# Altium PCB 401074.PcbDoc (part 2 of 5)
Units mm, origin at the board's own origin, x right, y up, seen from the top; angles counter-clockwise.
Board outline 70.15 x 35.15 mm, 6 copper layers (Top Layer, Mid-Layer1, Mid-Layer2, Mid-Layer3, Mid-Layer4, Bottom Layer), stack 1.549 mm thick; 239 components, 182 nets, 1034 pads, 1263 vias.
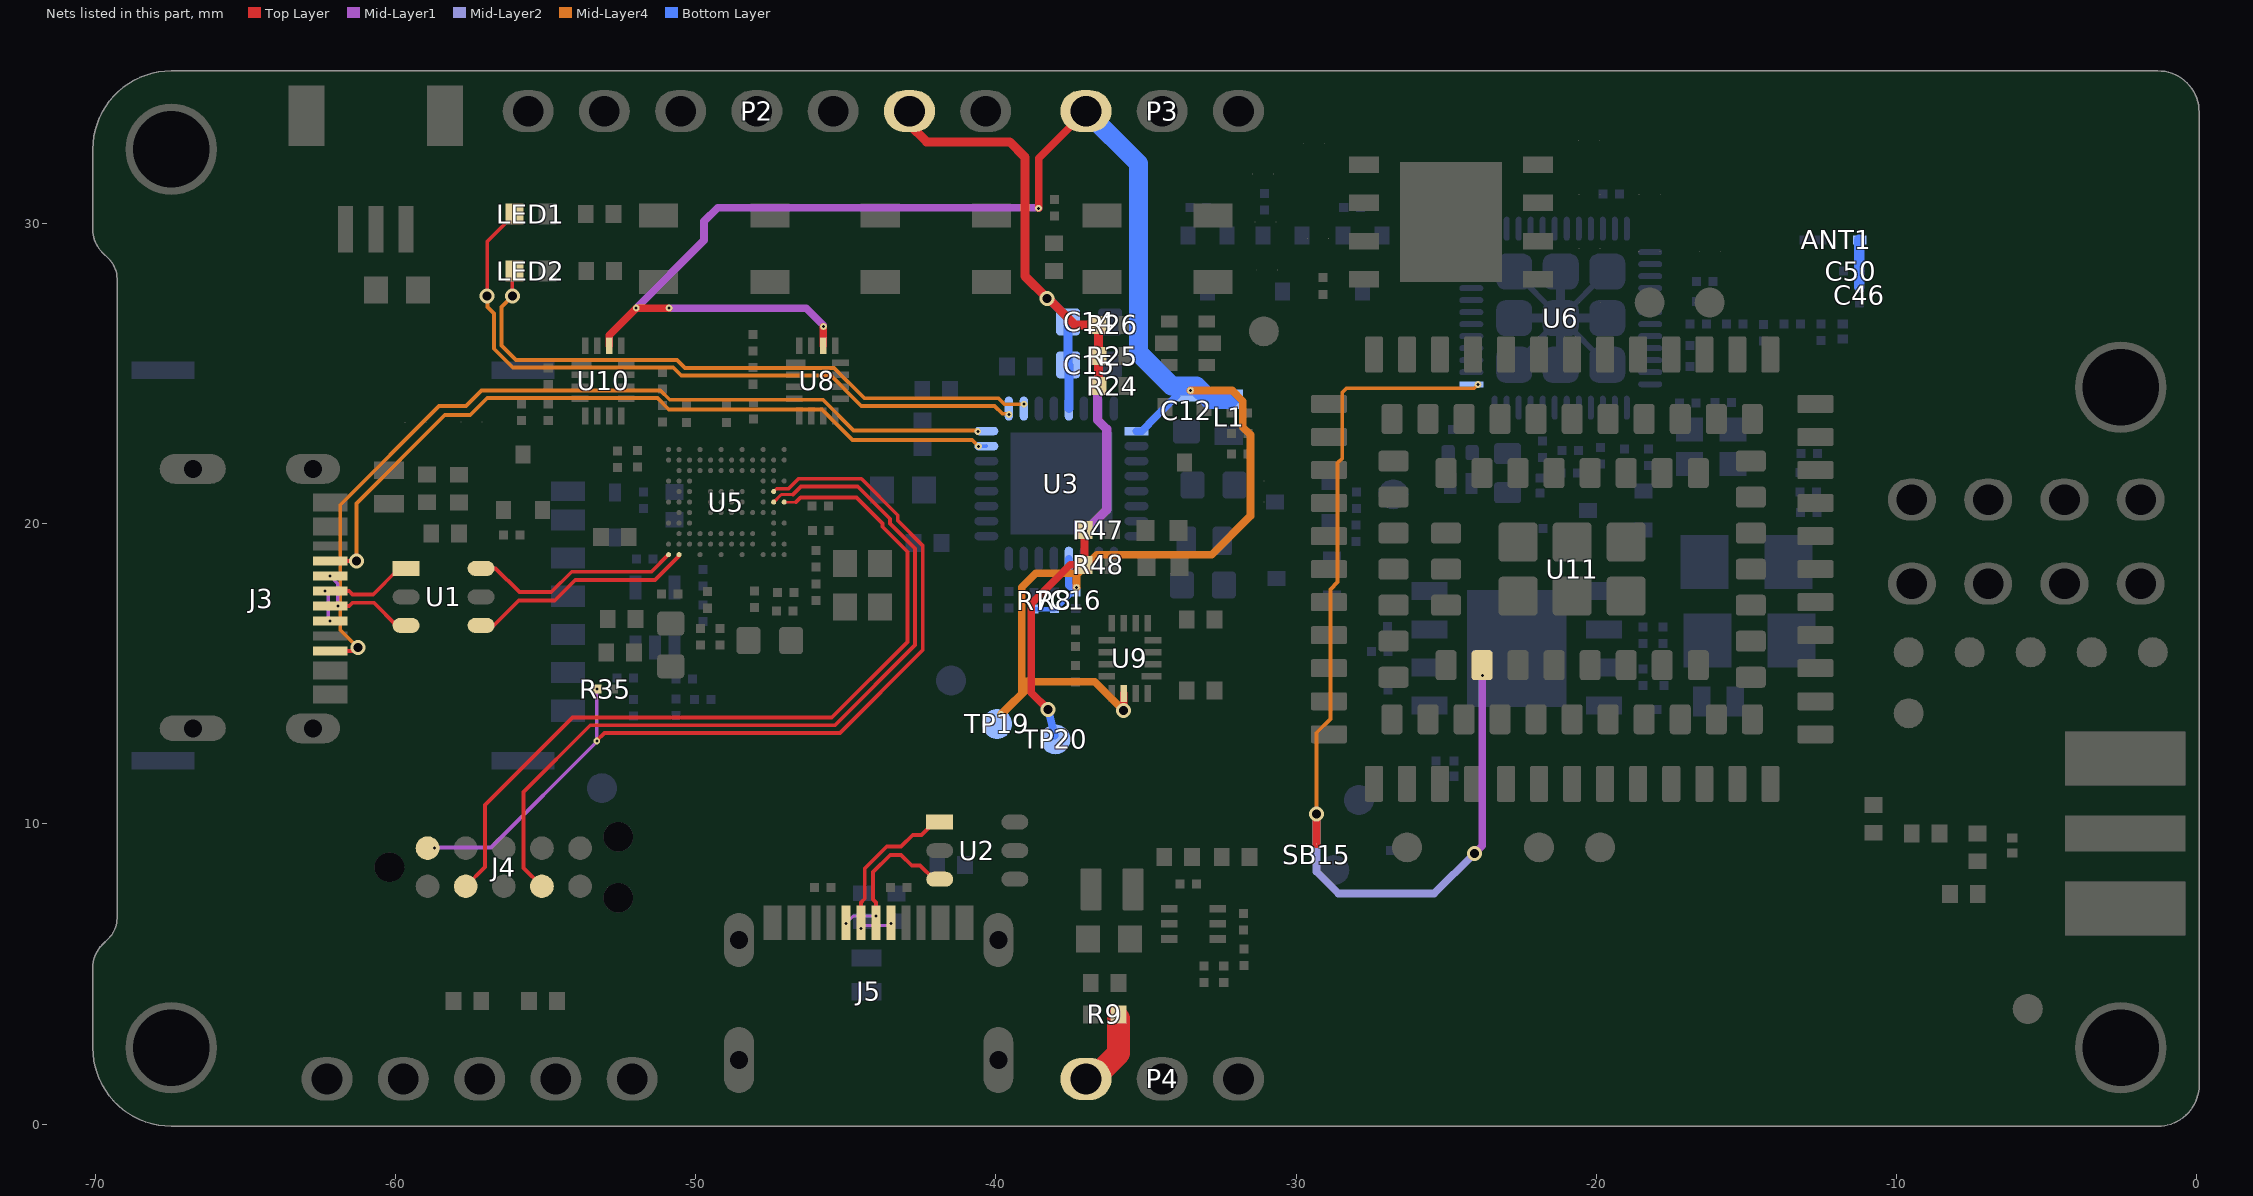
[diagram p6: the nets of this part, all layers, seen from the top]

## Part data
ANT1: library part "ANT 2P-2", "ANT"
ANT2: library part SMA_EDGE, "CON SMA RCPT STR 50OHM EDGE MNT", Manufacturer="SMA edge"
BUTTON1 BUTTON2 K3: library part 1414000721, "3.2*4.2*2.5mm", Manufacturer Part Number=BL-QC-3.2X4.2
C1 C4: library part 1405000464_1, "0.1uF/16V/10%/X7R", Manufacturer=Samsung, Manufacturer Part Number=CL05B104KO5NNNC
C2 C5 C17: library part 1405002483, "4.7uF/16V/20%/X5R", Manufacturer=Samsung, Manufacturer Part Number=CL05A475MO5NUNC
C3 C6: library part 1405000041, "0.1uF/16V/10%/X7R", Manufacturer=Yageo, Manufacturer Part Number=CC0402KRX7R7BB104
C7 C8: library part 1405002135, "1uF/25V/10%/X5R", Manufacturer=Samsung, Manufacturer Part Number=CL05A105KA5NQNC
C9 C10 C12 C13 C14 C15: library part 1405005588, "10uF/25V/20%/X5R", Manufacturer=Yageo, Manufacturer Part Number=CC0603MRX5R8BB106
C11: library part 1405005857, "2.2uF/16V/10%/X5R", Manufacturer=Viiyong, Manufacturer Part Number=V225K0402X5R160NNT
C16 C40 C41 C42 C44 C58: library part 1405001080, "0.1uF/10V/10%/X5R", Manufacturer=Walsin, Manufacturer Part Number=0201X104K100CT
C18: library part 1405004038, "1uF/16V/10%/X5R", Manufacturer=Samsung, Manufacturer Part Number=CL05A105KO5NNNC
C19: library part 1405004304, "20pF/50V/5%/C0G", Manufacturer=Viiyong, Manufacturer Part Number=V200J0201C0G500NAT
C20: library part 1405001346, "22uF/10V/20%/X5R", Manufacturer=Samsung, Manufacturer Part Number=CL10A226MP8NUN#
C21: library part 1405001308, "10uF/10V/20%/X5R", Manufacturer=Samsung, Manufacturer Part Number=CL05A106MP5NUNC
C22 C23 C28 C29 C30 C35 C61 C71 C76: library part 1405001272, "0.1uF/10V/10%/X5R", Manufacturer=Viiyong, Manufacturer Part Number=V104K0201X5R100NAT
C24 C25 C26 C31 C32 C36: library part 1405005056, "1uF/10V/20%/X5R", Manufacturer=Viiyong, Manufacturer Part Number=V105M0201X5R100NXT
C27: library part 1405004274, "2.2nF/16V/10%/X7R", Manufacturer=Yageo, Manufacturer Part Number=CC0201KRX7R7BB222
C33 C34: library part 1405005659, "4.7uF/10V/10%/X5R", Manufacturer=Viiyong, Manufacturer Part Number=V475K0402X5R100NCT
C37 C55 C56: library part 1405000464, "100pF/16V/10%/X7R", Manufacturer=Samsung, Manufacturer Part Number=CL05B104KO5NNNC
C38 C39 C57 C73 C74 C79: library part CAP-NBOM, Manufacturer=N.A.
C43: library part 1405001308_1, "10uF/10V/20%/X5R", Manufacturer=Samsung, Manufacturer Part Number=CL05A106MP5NUNC
C45 C51: library part 1405005059, "2.2uF/10V/20%/X5R", Manufacturer=Viiyong, Manufacturer Part Number=V225M0201X5R100NXT
C46 C50: library part 1405002000, "8pF/50V/0.1pF/C0G", Manufacturer=Murata, Manufacturer Part Number=GRM0335C1H8R0BA01D
C47: library part 1405002405, "2pF/50V/±0.1pF/GQC", Manufacturer=Viiyong, Manufacturer Part Number=V2R0B0201GQC500NAT
C48: library part 1405001154, "0.3pF/50V/±0.1pF/GQC", Manufacturer=Viiyong, Manufacturer Part Number=V0R3B0201GQC500NAT
C49: library part 1405002406, "1.5pF/50V/±0.1pF/GQC", Manufacturer=Viiyong, Manufacturer Part Number=V1R5B0201GQC500NAT
C52 C53: library part 1405005868, "10nF/25V/10%/X7R", Manufacturer=Viiyong, Manufacturer Part Number=V103K0201X7R250NAT
C54: library part 1405002488, "3.9pF/50V/±0.1pF/C0G", Manufacturer=Viiyong, Manufacturer Part Number=V3R9B0201C0G500NAT
C59 C60: library part 1405002417, "100uF/6.3V/20%/X5R", Manufacturer=Samsung, Manufacturer Part Number=CL31A107MQHNNNE
C62: library part 1405001363, "100pF/50V/5%/C0G", Manufacturer=Viiyong, Manufacturer Part Number=V101J0201C0G500NAT
C63 C68 C69 C70 C72 C75 C77 C78: library part 1405002411, "33pF/50V/5%/C0G", Manufacturer=Viiyong, Manufacturer Part Number=V330J0201C0G500NAT
C64: library part 1405005275, "8.2pF/50V/±0.1pF/C0G", Manufacturer=Yageo, Manufacturer Part Number=CC0201BRNPO9BN8R2
C65 C66 C80: library part 1405000291, "33pF/50V/5%/C0G", Manufacturer=Yageo, Manufacturer Part Number=CC0402JRNPO9BN330
C67: library part 1405005345, "4.7uF/6.3V/20%/X5R", Manufacturer=Samsung, Manufacturer Part Number=CL03A475MQ5C65C
D1 D2: library part 1409004319, Manufacturer=Walsin
D3: library part 1409000820_1, "5V/100W"
D4 D6: "5V/100W"
D5: "4.5V", Manufacturer=Walsin, Manufacturer Part Number=WS4.5DPVL
D7: library part 1409000207, "ESD", Manufacturer=Nexperia
FB1: library part 1404001917, Manufacturer=Murata
J2: library part 1416003652, "NANO SIM", Manufacturer=MUP
J3 J5: library part 1416004859, "USB2.0 TpyeC", Manufacturer=MUP, Manufacturer Part Number=MUP-U20402-01
J4: library part "10pin JTAG"
L1 L2: library part 1404000234, "2.2uH/20%/2.5*2*1.2/2.07A/0.166Ω", Manufacturer=Sunlord, Manufacturer Part Number=SWPA252012S2R2MT
L3: library part 1404002926, "2.2uH/20%/2.0*1.2*0.8/1.7A/146mΩ", Manufacturer=Scientic, Manufacturer Part Number=SKFB201208PA2R2M
L4 L5: library part L-NBOM, Manufacturer=N.A.
L6: library part 1404000149, "0603"
L7: library part 1404002414, "2.7nH/±0.1nH/500mA/0.2Ω", Manufacturer=Sunlord, Manufacturer Part Number=SDCL0603Q2N7BT02B03
L8 L9: library part 1404002487, "3.4nH/±0.1nH/450mA/0.25Ω", Manufacturer=Sunlord, Manufacturer Part Number=SDCL0603Q3N4BT02B03
L10: library part 1404002237, "90Ω/0.1A/3.8Ω", Manufacturer=Murata, Manufacturer Part Number=DLM0NSM900HY2#
LED1: library part 1409000384, "25mA/40mcd", Manufacturer=Everlight, Manufacturer Part Number=16-213SURC/S530-A3/TR8
LED2 LED6: library part 1409003070, "25mA/112-225mcd", Manufacturer=Everlight, Manufacturer Part Number=16-213/GHC-YR1S1N/3T
LED4: library part 1409000550, "25mA/100mcd,180mcd, 50mcd", Manufacturer=Everlight, Manufacturer Part Number=19-337/R6GHBHC-A01/2T
LED5: library part 1409000343, "25mA/28.5-72mcd", Manufacturer=Everlight, Manufacturer Part Number=16-213/BHC-AN1P2/3T
LOGO1: library part "WEEE Symbol 3x4.5mm", "WEEE Directive symbol", Manufacturer=N.A.
LOGO2: "Segger logo, small size", Manufacturer=N.A.
P3 P4: library part 1416001241, Manufacturer Part Number=CNT-M254-1*3-GS-6/3-01
Q1 Q2 Q3 Q4 Q7 Q8: library part 1412002244, "NMOS/20V/0.89A", Manufacturer=Willsemi
Q5 Q6: library part 1412002759, "NPN/200mA/40V/200mW", Manufacturer=MCC
R1: library part RES-NBOM_0603, Manufacturer=N.A.
R2 R3: library part 1408000316, "470Ω/5%", Manufacturer=Yageo, Manufacturer Part Number=RC0402JR-07470RL
R4 R45 R46: library part 1408001835, "47KΩ/1%", Manufacturer=Yageo, Manufacturer Part Number=RC0201FR-0747KL
R5 R43 R44: library part 1408002588, "4.7KΩ/1%", Manufacturer=Uniohm, Manufacturer Part Number=0201WMF4701TEE
R6 R9 R37: library part 1408001258, "0Ω/1%", Manufacturer=Yageo, Manufacturer Part Number=RC0402FR-070RL
R7 R8: library part 1408001391, "10KΩ/1%", Manufacturer=Yageo, Manufacturer Part Number=RC0201FR-0710KL
R10: library part 1408006147, "51K/5%", Manufacturer=Uniohm, Manufacturer Part Number=RJ0201-51K
R11: library part 1408002571, "100KΩ/1%", Manufacturer=Uniohm, Manufacturer Part Number=0201WMF1003TEE
R12: library part 1408006619, "18KΩ/1%", Manufacturer=Yageo, Manufacturer Part Number=RC0201FR-0718KL
R13: library part 1408006619_1, "750Ω/1%", Manufacturer=Yageo
R14 R16 R18: library part 1408006911, "150Ω/1%", Manufacturer=Yageo, Manufacturer Part Number=RC0201FR-07150RL
R15: library part 1408001252, "2.2Ω/1%", Manufacturer=Uniohm, Manufacturer Part Number=0402WGF220KTCE
R17 R27 R28 R29 R31 R53 R54: library part 1408001480, "1MΩ/1%", Manufacturer=Yageo, Manufacturer Part Number=RC0201FR-071ML
R19 R20 R22 R32: library part 1408001446, "100KΩ/5%", Manufacturer=Yageo, Manufacturer Part Number=RC0201JR-07100KL
R21 R39 R49: library part RES-NBOM_0201, Manufacturer=N.A.
R23: library part 1408001445, "1KΩ/5%", Manufacturer=Yageo, Manufacturer Part Number=RC0201JR-071KL
R24 R25 R26 R47 R48: library part 1408000315, "330Ω/5%", Manufacturer=Uniohm, Manufacturer Part Number=0402WGJ0331TCE
R30 R60: library part 1408001444, "10KΩ/5%", Manufacturer=Yageo, Manufacturer Part Number=RC0201JR-0710KL
R33 R34: library part 1408001425, "5.1KΩ/1%", Manufacturer=Yageo, Manufacturer Part Number=RC0201FR-075K1L
R35: library part 1408001446_1, "150Ω/5%", Manufacturer=Yageo
R38: library part 1408000158, "10K/5%", Manufacturer=Yageo, Manufacturer Part Number=RC0402JR-0710KL
R40 R41 R42 R50 R51 R52: library part 1408001481, "22Ω/1%", Manufacturer=Yageo, Manufacturer Part Number=RC0201FR-0722RL
R62 R63: library part 1408000461, "0Ω/5%", Manufacturer=Yageo, Manufacturer Part Number=RC0402JR-070RL
SB1 SB4 SB15 SB16: Manufacturer=N.A.
SB2 SB5 SB17 SB18 SB19 SB20 SB21 SB22: library part "Solderbridge Shorted 0.4mm", "Shorted Solderbridge", Manufacturer=N.A.
SB3 SB8 SB9 SB10 SB11 SB12 SB13: library part "Solderbridge 0.4mm", Manufacturer=N.A.
TP1 TP2 TP3 TP4 TP5 TP6 TP7 TP8 TP9 TP10 TP11 TP12 TP13 TP14 TP15 TP16 TP17 TP18 TP19 TP20: library part MARK, Manufacturer=N.A.
U1 U2: library part 1410003301, "USB", Manufacturer=ST
U3: "Li-Ion/Li-Polymer USB-C battery charger with high efficiency buck regulators, LDOs or load switches, LED drivers, TWI and VBUSOUT", Manufacturer="Nordic Semiconductor"
U4: library part SGM61020XKB6G/TR, Manufacturer="SG Micro"
U5: "Multi-protocol Bluetooth Low Energy, IEEE 802.15.4, ANT and 2.4GHz proprietary system-on-chip", Manufacturer="Nordic Semiconductor"
U6: "Multi-protocol Bluetooth Low Energy, IEEE 802.15.4 and 2.4GHz proprietary Wireless MCU", Manufacturer="Nordic Semiconductor"
U7: library part MX25R6435FZNIL0, "Ultra low power, 64M-bit, serial multi I/O flash memory", Manufacturer=Macronix
U8 U9 U10: "Data / Audio Low-Voltage Dual DPDT Analog Switch", Manufacturer=Onsemi
U11: library part nRF93M1-LABA_V02, Manufacturer="Nordic Semiconductor"
U12: library part 1409000217, "7.14V/600W", Manufacturer=Onsemi
U13: library part QUAD_EUICC
X1 X2: library part 1413001678, "8pF/32MHz/10PPM/-40~85℃", Manufacturer Part Number=9S32000073

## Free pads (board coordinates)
  oval 1x2.2 on Top Paste: 2(-48.558,2.129) 3(-39.918,2.129)
  oval 2.2x0.85 on Top Paste: 4(-66.747,13.18)
  oval 2.2x1 on Top Paste: 5(-66.747,21.82)
  oval 1.8x1 on Top Paste: 6(-62.747,21.82) 7(-62.747,13.18)
  oval 1x1.8 on Top Paste: 8(-39.918,6.129) 9(-48.558,6.129)
  rect 3.4x3.4 smd far side: 10(-37.818,21.328)
  round 0.3 on Mech16: 29(-6.5,31.676)
  round 3.048 hole 2.54: ""(-67.46,32.46) ""(-67.46,2.54) ""(-2.54,24.54) ""(-2.54,2.54)

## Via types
v1: diameter 0.23, hole 0.1, Top Layer to Mid-Layer1, tented both sides, 505 vias
v2: diameter 0.5, hole 0.3, Top Layer to Bottom Layer, tented both sides, 430 vias
v3: diameter 0.23, hole 0.1, Mid-Layer4 to Bottom Layer, tented both sides, 176 vias
v4: diameter 0.23/0.23 (per signal layer), hole 0.1, Mid-Layer4 to Bottom Layer, tented both sides, 144 vias
v5: diameter 0.5, hole 0.3, Top Layer to Bottom Layer, tented top, 7 vias
v6: diameter 0.4, hole 0.25, Top Layer to Bottom Layer, tented both sides, 1 vias

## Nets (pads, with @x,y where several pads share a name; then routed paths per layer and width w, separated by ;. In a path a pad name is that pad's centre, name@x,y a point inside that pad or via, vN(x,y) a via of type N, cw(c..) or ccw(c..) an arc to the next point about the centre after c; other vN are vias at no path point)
1V8: C12.2 C16.2 L1.2 P3.1 R7.2 R8.1 TP19.1 U3.1 U3.12 U8.14 U9.14 U10.14 | length 70.2
  Top Layer w0.254: U10.14@-52.879,25.918 -52.879,26.269 v1(-51.978,27.171) v1(-50.893,27.171) ; U8.14@-45.747,25.918 v1(-45.747,26.556) ; v1(-38.574,30.498) -38.574,32.161 P3.1@-37,33.735 ; v2(-35.746,13.767) -35.738,13.775 U9.14@-35.738,14.34
  Mid-Layer1 w0.254: v1(-51.978,27.171) -49.721,29.428 -49.721,30.06 -49.26,30.521 -38.597,30.521 v1(-38.574,30.498) ; v1(-50.893,27.171) -46.322,27.171 -45.747,26.596 v1(-45.747,26.556)
  Mid-Layer4 w0.254: v3(-39.829,13.638) -38.847,14.62 -38.847,14.672 ; v3(-37.314,17.866) -37.314,18.286 -37.256,18.344 ; v2(-35.746,13.767) -36.714,14.735 -38.847,14.735 ; v3(-33.524,24.429) -32.13,24.429 -31.775,24.074 -31.775,23.211 -31.52,22.957 -31.52,20.251 -32.809,18.962 -36.638,18.962 -37.256,18.344 ; -39.137,14.672 -39.071,14.737 -38.847,14.737 -38.847,14.735 ; -39.137,14.672 -39.137,14.382 -38.847,14.672 ; -39.137,14.672 -39.137,17.873 -38.665,18.344 -37.256,18.344 ; -38.847,14.672 -38.847,14.735
  Bottom Layer w0.152: R7.2@-38.727,17.138 R8.1@-38.041,17.138 ; R8.1@-38.041,17.162 -37.98,17.162 -37.423,17.719 -37.446,17.742 -37.321,17.866 v3(-37.314,17.866)
  Bottom Layer w0.254: U3.12@-37.568,18.828 -37.568,17.947 -37.446,17.825 -37.404,17.866 C16.2@-37.321,17.866 ; U3.1@-35.318,23.078 -35.14,23.078 -34.907,23.31 -34.907,23.319 C12.2@-33.971,24.255 ; L1.2@-32.358,24.255 -32.156,24.255 L1.2@-32.002,24.101
  Bottom Layer w0.635: P3.1@-37,33.735 -35.247,31.982 -35.247,25.68 -34.145,24.578 -33.524,24.578 -33.321,24.578 -32.882,24.139 L1.2@-32.241,24.139
3V3: C14.2 C15.2 P2.6 R24.2 R25.2 R26.2 R47.2 R48.2 TP20.1 U3.29 | length 31.2
  Top Layer w0.254: v2(-38.261,13.805) -38.818,14.362 -38.818,17.323 -37.52,18.621 R48.2@-37.047,18.621 R47.2@-37.047,19.777
  Top Layer w0.305: P2.6@-42.878,33.735 -42.878,33.279 -42.308,32.708 -39.542,32.708 -39.031,32.197 -39.031,28.238 v2(-38.295,27.501) -38.261,27.501 -37.374,26.613 R26.2@-36.584,26.613 -36.584,24.531 v1(-36.61,24.505)
  Mid-Layer1 w0.305: v1(-37.016,19.747) -36.307,20.456 -36.307,23.142 -36.61,23.445 v1(-36.61,24.505)
  Bottom Layer w0.254: v2(-38.261,13.805) TP20.1@-38.041,12.934
  Bottom Layer w0.305: v2(-38.295,27.501) -38.261,27.501 -37.594,26.834 C14.2@-37.594,26.714 C15.2@-37.594,25.284 -37.568,25.258 U3.29@-37.568,23.828
3V8: P4.1 R9.2 | length 2.7
  Top Layer w0.762: P4.1@-37,1.265 -35.91,2.355 R9.2@-35.91,3.512
ANT: ANT1.1 C46.2 C50.2 | length 1.6
  Bottom Layer w0.356: C46.2@-11.244,27.882 ANT1.1@-11.244,29.444
BOOT: SB15.1 U6.1 U11.82 | length 34.1
  Top Layer w0.254: SB15.1@-29.32,9.325 v2(-29.32,10.329)
  Mid-Layer1 w0.254: v2(-24.065,9.008) -23.799,9.274 v1(-23.799,14.945)
  Mid-Layer4 w0.127: v2(-29.32,10.329) -29.32,13.033 -28.86,13.492 -28.86,17.807 -28.617,18.05 -28.617,22.015 -28.464,22.168 -28.464,24.36 -28.319,24.505 -24.069,24.505 v3(-23.948,24.626)
  Mid-Layer2 w0.254: v2(-29.32,10.329) -29.32,8.398 -28.599,7.678 -25.395,7.678 v2(-24.065,9.008)
CC1: J3.A5 U3.23 | length 26
  Top Layer w0.127: J3.A5@-62.172,18.75 -62.114,18.692 -62.026,18.78 -61.996,18.75 v2(-61.296,18.75)
  Mid-Layer4 w0.127: v2(-61.296,18.75) -61.296,20.669 -58.354,23.611 -57.507,23.611 -56.942,24.175 -51.709,24.175 -51.274,24.175 -50.893,23.794 -45.796,23.794 -44.78,22.778 -40.788,22.778 v4(-40.582,22.572)
  Bottom Layer w0.127: v4(-40.582,22.572) U3.23@-40.318,22.578
CC2: J3.B5 U3.24 | length 29.3
  Top Layer w0.127: J3.B5@-62.172,15.75 -61.366,15.75 v2(-61.251,15.865)
  Mid-Layer4 w0.127: v2(-61.251,15.865) -61.835,16.448 -61.835,20.619 -58.546,23.909 -57.651,23.909 -57.131,24.429 -51.173,24.429 -50.863,24.119 -45.762,24.119 -44.737,23.094 v4@-40.65,23.094
  other v4: -40.603,23.069
CHARGE: LED2.K U3.26 | length 20.9
  Top Layer w0.127: v2(-56.104,27.575) -56.104,28.339 LED2.K@-56.034,28.409
  Mid-Layer4 w0.127: v2(-56.104,27.575) -56.466,27.213 -56.466,25.925 -55.988,25.447 -50.623,25.447 -50.359,25.183 -45.389,25.183 -44.378,24.172 -39.912,24.172 -39.713,23.972 v4(-39.065,23.972)
D1_N: J3.A7 J3.B7 U1.3 | length 4
  Top Layer w0.127: J3.A7@-62.172,17.25 -61.918,17.25 -61.534,17.25 -61.424,17.36 -60.713,17.36 -59.959,16.606 U1.3@-59.642,16.606
  Mid-Layer1 w0.102: v1(-62.172,18.25) -61.918,17.996 v1(-61.918,17.244)
D1_P: J3.A6 J3.B6 U1.1 | length 4
  Top Layer w0.127: J3.A6@-62.172,17.75 -61.534,17.75 -61.424,17.64 -60.738,17.64 -59.936,18.443 -59.706,18.443 U1.1@-59.642,18.506
  Mid-Layer1 w0.102: v1(-62.347,17.755) -62.236,17.644 -62.236,16.813 v1(-62.172,16.75)
D2_N: J5.A7 J5.B7 U2.3 | length 5.7
  Top Layer w0.127: J5.A7@-43.993,6.68 -43.993,7.374 -43.987,7.38 -44.088,7.48 -44.088,8.393 -43.518,8.962 -43.155,8.962 -42.804,8.611 -42.522,8.611 -42.063,8.152 U2.3@-41.87,8.152
  Mid-Layer1 w0.102: v1(-44.993,6.68) -44.739,6.934 v1(-43.987,6.934)
D2_P: J5.A6 J5.B6 U2.1 | length 6.1
  Top Layer w0.127: J5.A6@-44.487,6.741 -44.449,6.779 -44.449,6.995 -44.487,7.033 -44.487,7.38 -44.367,7.499 -44.367,8.508 -43.634,9.242 -43.155,9.242 -42.77,9.627 -42.473,9.627 -42.047,10.052 U2.1@-41.87,10.052
  Mid-Layer1 w0.102: v1(-44.498,6.505) -44.386,6.617 -43.556,6.617 v1(-43.493,6.68)
D_N: U1.4 U5.A11 | length 7.6
  Top Layer w0.127: U1.4@-57.142,16.606 -56.721,16.606 -55.892,17.436 -54.691,17.436 -54.011,18.116 -51.352,18.116 -50.55,18.917 U5.A11@-50.55,18.962
D_P: U1.6 U5.A12 | length 7.1
  Top Layer w0.127: U1.6@-57.142,18.506 -56.662,18.506 -55.871,17.715 -54.806,17.715 -54.126,18.395 -51.467,18.395 U5.A12@-50.9,18.962
DBGR_RESET: J4.10 R35.2 U5.G2 | length 30.4
  Top Layer w0.102: U5.G2@-47.4,21.062 -47.306,21.157 -46.906,21.157
  Top Layer w0.127: v1@-53.292,12.769 -53.035,13.026 -45.191,13.026 -42.438,15.779 -42.438,19.272 -43.268,20.102 -43.268,20.276 -44.481,21.488 -46.575,21.488 -46.906,21.157
  Mid-Layer1 w0.127: v1@-58.697,9.206 -56.815,9.206 -53.292,12.729 v1(-53.292,12.762) ; v1(-53.292,12.762) v1(-53.291,14.487)
  other v1: -58.698,9.198
DBGR_SWDCLK: J4.4 U5.F2 | length 27.5
  Top Layer w0.102: U5.F2@-47.4,20.712 -47.147,20.966 -46.756,20.966
  Top Layer w0.127: J4.4@-55.118,7.917 -55.728,8.527 -55.728,11.061 -53.509,13.28 -45.362,13.28 -42.692,15.95 -42.692,19.167 -43.522,19.996 -43.522,20.157 -44.6,21.234 -45.178,21.234 -46.488,21.234 -46.756,20.966
DBGR_SWDIO: J4.2 U5.F1 | length 27.3
  Top Layer w0.089: U5.F1@-47.05,20.712 -46.655,20.712
  Top Layer w0.127: J4.2@-57.658,7.917 -57.012,8.563 -57.012,10.623 -54.101,13.534 -45.467,13.534 -42.946,16.055 -42.946,19.061 -43.776,19.891 -43.776,19.995 -44.646,20.865 -45.178,20.865 -46.502,20.865 -46.655,20.712
ERROR: LED1.K U3.25 | length 23
  Top Layer w0.127: v2(-56.942,27.578) -56.942,29.392 LED1.K@-56.034,30.3
  Mid-Layer4 w0.127: v2(-56.942,27.578) -56.936,27.572 -56.936,27.216 -56.72,26.999 -56.72,25.82 -56.093,25.193 -50.744,25.193 -50.481,24.929 -45.495,24.929 -44.483,23.918 -40.043,23.918 -39.779,23.654 -39.59,23.654 v4(-39.568,23.631)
